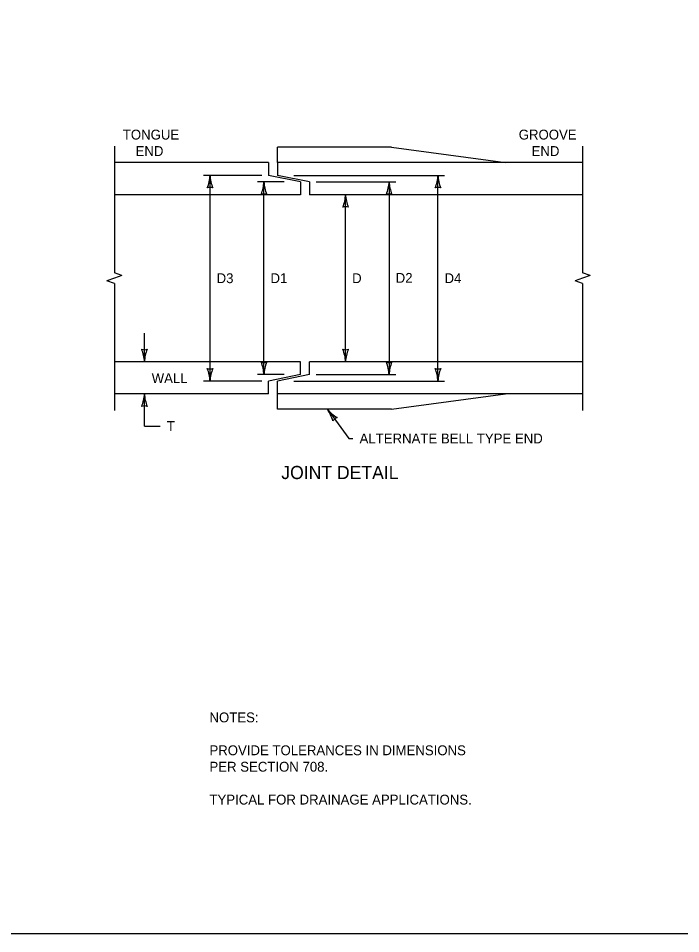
# Model space of a CAD drawing. Extents: x 49991.4 to 50021, y 49987.6 to 50011.4.
# Drawn here: x 50008.69 to 50012.72, y 49987.8 to 49993.37 of the extents above; entities that cross this region are included whole.
import ezdxf

# ---------------------------------------------------------------- set-up
doc = ezdxf.new("R2010")
doc.units = 0
for name, color, linetype in [('Level 1', 7, 'Continuous'), ('Level 2', 7, 'Continuous'), ('Level 3', 7, 'Continuous'), ('Level 4', 7, 'Continuous'), ('Level 6', 7, 'Continuous')]:
    doc.layers.add(name, color=color, linetype=linetype)

msp = doc.modelspace()

# ---------------------------------------------------------------- linework, layer by layer
at = {"layer": 'Level 1'}
for p, q in [((50010.212, 49992.4891), (50009.2739, 49992.4891)), ((50010.212, 49992.4891), (50010.212, 49992.4109)), ((50010.2661, 49992.4891), (50010.2661, 49992.4109)), ((50012.1233, 49992.4891), (50010.2661, 49992.4891)), ((50010.4074, 49992.3719), (50010.212, 49992.4109)), ((50010.4615, 49992.3719), (50010.2661, 49992.4109)), ((50010.4074, 49992.3719), (50010.4074, 49992.2937)), ((50010.4615, 49992.3719), (50010.4615, 49992.2937)), ((50010.4074, 49992.2937), (50009.2739, 49992.2937)), ((50012.1233, 49992.2937), (50010.4615, 49992.2937)), ((50010.4074, 49991.2775), (50009.2739, 49991.2775)), ((50010.4074, 49991.1993), (50010.4074, 49991.2775)), ((50010.4615, 49991.1993), (50010.4615, 49991.2775)), ((50012.1233, 49991.2775), (50010.4615, 49991.2775)), ((50010.4074, 49991.1993), (50010.212, 49991.1602)), ((50010.4615, 49991.1993), (50010.2661, 49991.1602)), ((50010.212, 49991.082), (50010.212, 49991.1602)), ((50010.2661, 49991.082), (50010.2661, 49991.1602)), ((50010.212, 49991.082), (50009.2739, 49991.082)), ((50012.1233, 49991.082), (50010.2661, 49991.082))]:
    msp.add_line(p, q, dxfattribs=at)
msp.add_lwpolyline([(49999.3835, 49998.9992), (50016.7501, 49998.9992), (50016.7501, 49987.7988), (49999.3835, 49987.7988)], close=True, dxfattribs=at)
at = {"layer": 'Level 3'}
for p, q in [((50010.172, 49992.4109), (50009.8162, 49992.4109)), ((50009.8562, 49991.1602), (50009.8562, 49992.4109)), ((50010.3661, 49992.4109), (50011.2829, 49992.4109)), ((50011.2429, 49991.1602), (50011.2429, 49992.4109)), ((50010.3074, 49992.3719), (50010.1441, 49992.3719)), ((50010.1841, 49991.1993), (50010.1841, 49992.3719)), ((50010.5015, 49992.3719), (50010.9857, 49992.3719)), ((50010.9457, 49992.3719), (50010.9457, 49991.1993)), ((50010.6807, 49991.2775), (50010.6807, 49992.2937)), ((50009.4571, 49991.2775), (50009.4571, 49991.4509)), ((50010.3074, 49991.1993), (50010.1441, 49991.1993)), ((50010.5015, 49991.1993), (50010.9857, 49991.1993)), ((50010.172, 49991.1602), (50009.8162, 49991.1602)), ((50010.3661, 49991.1602), (50011.2829, 49991.1602)), ((50009.4571, 49990.8865), (50009.4571, 49991.082)), ((50010.5702, 49990.9882), (50010.701, 49990.8108)), ((50009.4571, 49990.8865), (50009.5533, 49990.8865)), ((50010.701, 49990.8108), (50010.726, 49990.8108))]:
    msp.add_line(p, q, dxfattribs=at)
for centre, radius, start, end in [((50009.6341, 49992.4201), 0.2223, 337.456, 357.6395), ((50010.0889, 49992.4224), 0.233, 182.8273, 202.0772), ((50011.0208, 49992.4201), 0.2223, 337.456, 357.6395), ((50011.4756, 49992.4224), 0.233, 182.8273, 202.0772), ((50009.8562, 49992.2827), 0.0548, 72.1388, 107.8612), ((50009.962, 49992.3811), 0.2223, 337.456, 357.6395), ((50010.4168, 49992.3834), 0.233, 182.8273, 202.0772), ((50010.7236, 49992.3811), 0.2223, 337.456, 357.6395), ((50011.1784, 49992.3834), 0.233, 182.8273, 202.0772), ((50011.2429, 49992.2827), 0.0548, 72.1388, 107.8612), ((50010.1841, 49992.2437), 0.0548, 72.1388, 107.8612), ((50010.4586, 49992.3029), 0.2223, 337.456, 357.6395), ((50010.9134, 49992.3052), 0.233, 182.8273, 202.0772), ((50010.9457, 49992.2437), 0.0548, 72.1388, 107.8612), ((50010.6807, 49992.1655), 0.0548, 72.1388, 107.8612), ((50009.4571, 49991.4057), 0.0548, 252.1388, 287.8612), ((50009.2244, 49991.266), 0.233, 2.8273, 22.0772), ((50009.6792, 49991.2684), 0.2223, 157.456, 177.6395), ((50010.6807, 49991.4057), 0.0548, 252.1388, 287.8612), ((50010.448, 49991.266), 0.233, 2.8273, 22.0772), ((50010.9028, 49991.2684), 0.2223, 157.456, 177.6395), ((50009.8562, 49991.2884), 0.0548, 252.1388, 287.8612), ((50009.6235, 49991.1487), 0.233, 2.8273, 22.0772), ((50010.0783, 49991.1511), 0.2223, 157.456, 177.6395), ((50010.1841, 49991.3275), 0.0548, 252.1388, 287.8612), ((50009.9514, 49991.1878), 0.233, 2.8273, 22.0772), ((50010.4062, 49991.1902), 0.2223, 157.456, 177.6395), ((50010.9457, 49991.3275), 0.0548, 252.1388, 287.8612), ((50010.713, 49991.1878), 0.233, 2.8273, 22.0772), ((50011.1678, 49991.1902), 0.2223, 157.456, 177.6395), ((50011.2429, 49991.2884), 0.0548, 252.1388, 287.8612), ((50011.0102, 49991.1487), 0.233, 2.8273, 22.0772), ((50011.465, 49991.1511), 0.2223, 157.456, 177.6395), ((50009.235, 49991.0912), 0.2223, 337.456, 357.6395), ((50009.6898, 49991.0935), 0.233, 182.8273, 202.0772), ((50009.4571, 49990.9538), 0.0548, 72.1388, 107.8612), ((50010.3885, 49990.8601), 0.2223, 14.9954, 35.179), ((50010.7477, 49991.1391), 0.233, 220.3667, 239.6166), ((50010.6483, 49990.8866), 0.0548, 109.6783, 145.4006)]:
    msp.add_arc(centre, radius, start, end, dxfattribs=at)
at = {"layer": 'Level 4'}
for p, q in [((50010.9602, 49992.5829), (50010.2661, 49992.5829)), ((50010.2661, 49992.4891), (50010.2661, 49992.5829)), ((50010.9602, 49992.5829), (50011.6543, 49992.4891)), ((50010.2661, 49990.9882), (50010.2661, 49991.082)), ((50010.9602, 49990.9882), (50011.6543, 49991.082)), ((50010.9602, 49990.9882), (50010.2661, 49990.9882))]:
    msp.add_line(p, q, dxfattribs=at)
at = {"layer": 'Level 6'}
for p, q in [((50009.2739, 49992.5891), (50009.2739, 49991.818)), ((50012.1233, 49992.5891), (50012.1233, 49991.818)), ((50009.2739, 49991.7856), (50009.2282, 49991.7694)), ((50009.3196, 49991.8018), (50009.2739, 49991.818)), ((50009.3196, 49991.8018), (50009.2739, 49991.7856)), ((50012.1233, 49991.7856), (50012.0776, 49991.7694)), ((50012.169, 49991.8018), (50012.1233, 49991.818)), ((50012.169, 49991.8018), (50012.1233, 49991.7856)), ((50009.2739, 49991.7532), (50009.2282, 49991.7694)), ((50009.2739, 49991.7532), (50009.2739, 49990.982)), ((50012.1233, 49991.7532), (50012.0776, 49991.7694)), ((50012.1233, 49991.7532), (50012.1233, 49990.982))]:
    msp.add_line(p, q, dxfattribs=at)

# ---------------------------------------------------------------- texts
at = {"layer": 'Level 2'}
for s, height, p in [('TONGUE', 0.06, (50009.3254, 49992.6291)), ('GROOVE', 0.06, (50011.7345, 49992.6291)), ('END', 0.06, (50009.4032, 49992.5291)), ('END', 0.06, (50011.8126, 49992.5291)), ('D3', 0.06, (50009.8962, 49991.7556)), ('D1', 0.06, (50010.2241, 49991.7556)), ('D', 0.06, (50010.7207, 49991.7556)), ('D2', 0.06, (50010.9857, 49991.7576)), ('D4', 0.06, (50011.2829, 49991.7556)), ('WALL', 0.06, (50009.5012, 49991.1476)), ('T', 0.06, (50009.5933, 49990.8565)), ('ALTERNATE BELL TYPE END', 0.06, (50010.766, 49990.7808)), ('JOINT DETAIL', 0.08, (50010.2897, 49990.564)), ('NOTES:', 0.06, (50009.8526, 49989.0843)), ('PROVIDE TOLERANCES IN DIMENSIONS', 0.06, (50009.8526, 49988.8843)), ('PER SECTION 708.', 0.06, (50009.8526, 49988.7843)), ('TYPICAL FOR DRAINAGE APPLICATIONS.', 0.06, (50009.8526, 49988.5843))]:
    msp.add_text(s, height=height, dxfattribs=at).set_placement(p)

doc.saveas('drawing.dxf')
